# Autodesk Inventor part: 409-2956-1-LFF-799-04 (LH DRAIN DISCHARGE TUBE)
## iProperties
Created: 2010-11
Part Number: 409-2956-1-LFF-799-04 (LH DRAIN DISCHARGE TUBE)
Material: 3/4" OD TUBE - SS
Document SubType Name: Modeling
Designer: S. Boerckel
Engineer: Steve Boerckel
Mass: 731.966 g
Surface Area: 1099.2 cm^2
Volume: 90.5898 cm^3
Density: 8.08 g/cm^3
Description: DRAIN TUBING
Length: 39.521 in
Author: S. Boerckel
Revision Number: 0
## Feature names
1. Sweep2
